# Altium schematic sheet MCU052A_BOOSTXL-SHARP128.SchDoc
size 431 x 279 mm; Date: Not shown in title block; ApprovedBy: Not shown in title block; CheckedBy: Not shown in title block; Author: Not shown in title block; CompanyName: Not shown in title block; Engineer: Not shown in title block; Organization: Not shown in title block; Address1: Not shown in title block; Address2: Not shown in title block; Address3: Not shown in title block; Address4: Not shown in title block; DocumentNumber: 1; Revision: Use project parameter SCH_Rev; SheetNumber: 1; SheetTotal: 2; PageSetup: Record=PageOptions¦CenterHorizontal=True¦CenterVertical=True¦PrintScale=1.00¦XCorrection=1.00¦YCorrection=1.00¦PrintKind=0¦BorderSize=5000000¦LeftOffset=0¦BottomOffset=0¦Orientation=2¦PaperLength=1000¦PaperWidth=1000¦Scale=100¦PaperSource=15¦PrintQuality=600¦MediaType=1¦DitherType=10¦PaperKind=Letter¦PrintScaleMode=1
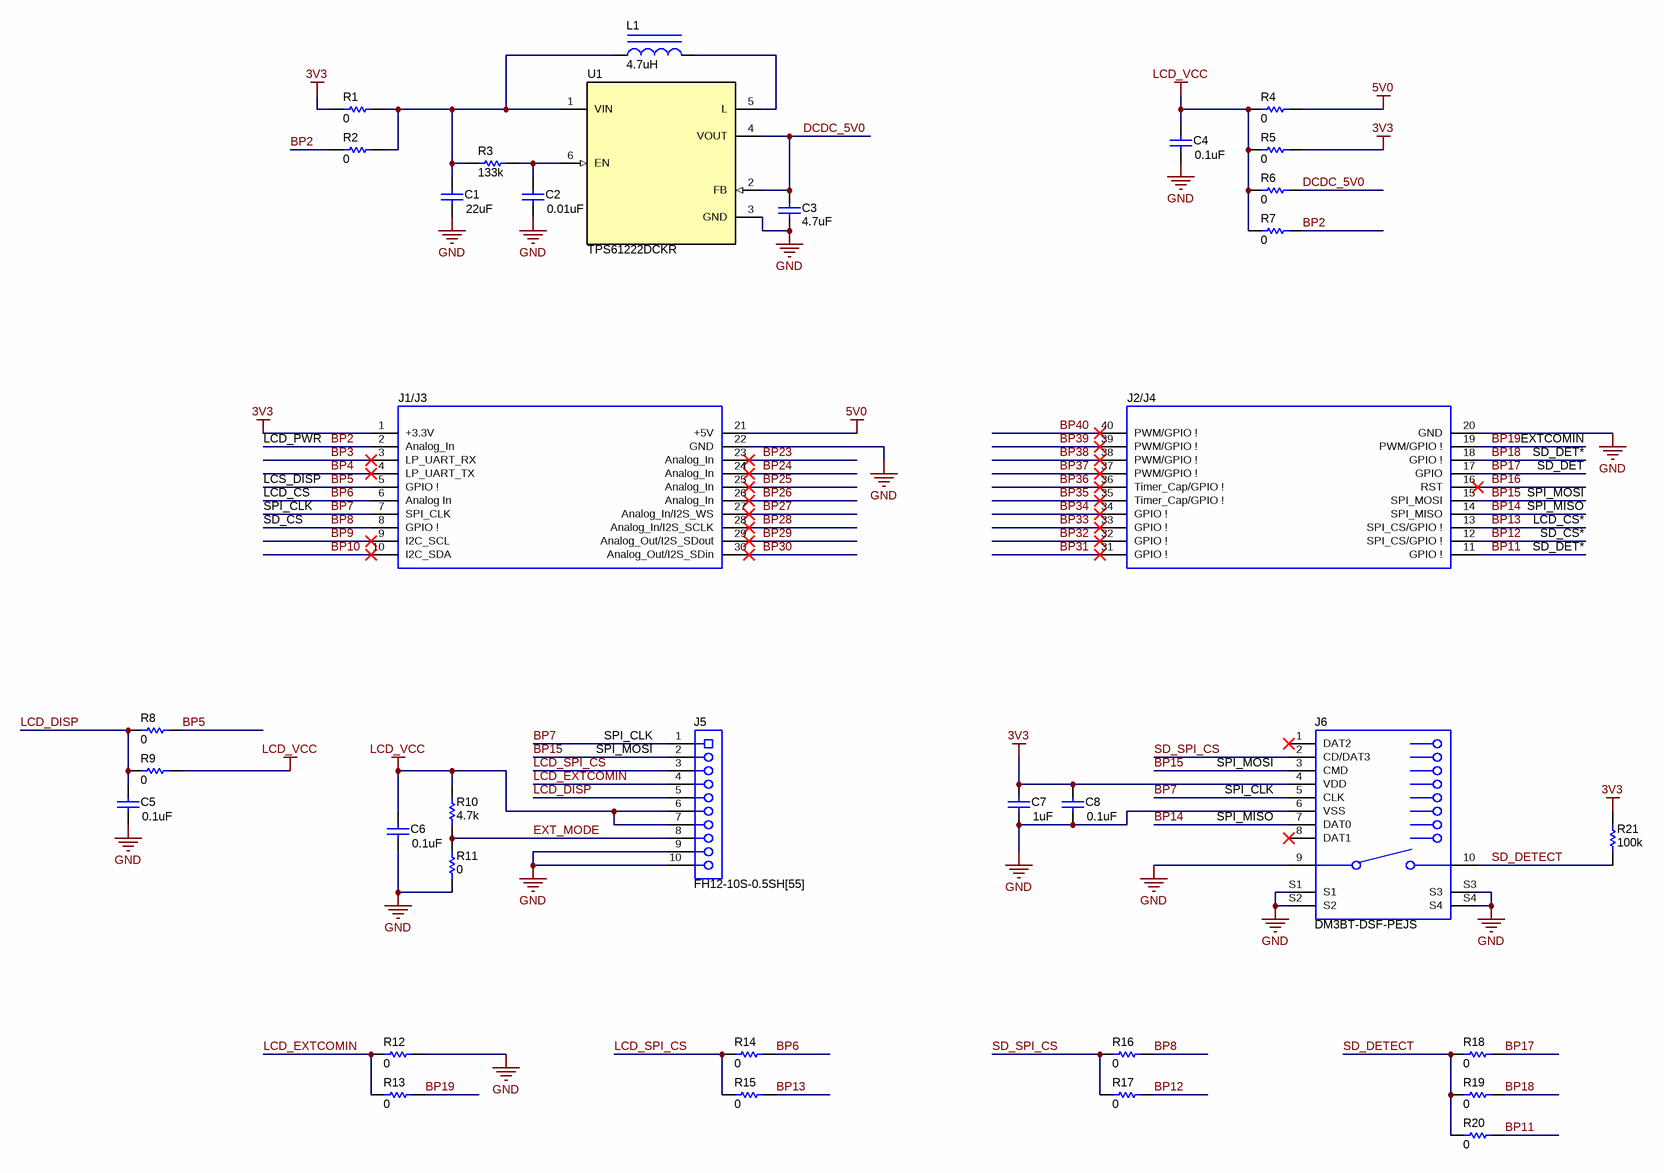
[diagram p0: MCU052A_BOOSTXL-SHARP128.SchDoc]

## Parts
C1  ValueDisplayed: 22uF  [0603]  (hidden comment: GRM188R61A226ME15D)
C2  ValueDisplayed: 0.01uF  [0603]  (hidden comment: GRM188R71E103KA01D)
C3  ValueDisplayed: 4.7uF  [0603]  (hidden comment: GRM188C71A475KE11D)
C4  ValueDisplayed: 0.1uF  [0402]  (hidden comment: GRM155R71A104KA01D)
C5  ValueDisplayed: 0.1uF  [0402]  (hidden comment: GRM155R71A104KA01D)
C6  ValueDisplayed: 0.1uF  [0402]  (hidden comment: GRM155R71A104KA01D)
C7  ValueDisplayed: 1uF  [0603]  (hidden comment: GRM188R71C105KA12D)
C8  ValueDisplayed: 0.1uF  [0402]  (hidden comment: GRM155R71A104KA01D)
J1/J3  SSQ-110-03-T-D  [BoosterPack_40pin_J1J3]  (value not drawn)
J2/J4  SSQ-110-03-T-D  [BoosterPack_40pin_J2J4]  (value not drawn)
J5  FH12-10S-0.5SH[55]  [Hirose_FH12-10S-0_5SH[55]]
J6  DM3BT-DSF-PEJS  [Hirose_DM3BT-DSF-PEJS]
L1  ValueDisplayed: 4.7uH  [EPL3015]  (hidden comment: EPL3015-472MLB)
R1  ValueDisplayed: 0  [0603]  (hidden comment: CRCW06030000Z0EA)
R2  ValueDisplayed: 0  [0603]  (hidden comment: CRCW06030000Z0EA)
R3  ValueDisplayed: 133k  [0603]  (hidden comment: CRCW0603133KFKEA)
R4  ValueDisplayed: 0  [0603]  (hidden comment: CRCW06030000Z0EA)
R5  ValueDisplayed: 0  [0603]  (hidden comment: CRCW06030000Z0EA)
R6  ValueDisplayed: 0  [0603]  (hidden comment: CRCW06030000Z0EA)
R7  ValueDisplayed: 0  [0603]  (hidden comment: CRCW06030000Z0EA)
R8  ValueDisplayed: 0  [0603]  (hidden comment: CRCW06030000Z0EA)
R9  ValueDisplayed: 0  [0603]  (hidden comment: CRCW06030000Z0EA)
R10  ValueDisplayed: 4.7k  [0603]  (hidden comment: CRCW06034K70JNEA)
R11  ValueDisplayed: 0  [0603]  (hidden comment: CRCW06030000Z0EA)
R12  ValueDisplayed: 0  [0603]  (hidden comment: CRCW06030000Z0EA)
R13  ValueDisplayed: 0  [0603]  (hidden comment: CRCW06030000Z0EA)
R14  ValueDisplayed: 0  [0603]  (hidden comment: CRCW06030000Z0EA)
R15  ValueDisplayed: 0  [0603]  (hidden comment: CRCW06030000Z0EA)
R16  ValueDisplayed: 0  [0603]  (hidden comment: CRCW06030000Z0EA)
R17  ValueDisplayed: 0  [0603]  (hidden comment: CRCW06030000Z0EA)
R18  ValueDisplayed: 0  [0603]  (hidden comment: CRCW06030000Z0EA)
R19  ValueDisplayed: 0  [0603]  (hidden comment: CRCW06030000Z0EA)
R20  ValueDisplayed: 0  [0603]  (hidden comment: CRCW06030000Z0EA)
R21  ValueDisplayed: 100k  [0603]  (hidden comment: CRCW0603100KFKEA)
U1  TPS61222DCKR  [DCK0006A_N]

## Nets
3V3: C7.1 C8.1 J1/J3.1(+3.3V) J6.4(VDD) R1.1 R5.2 R21.2
5V0: J1/J3.21(+5V) R4.2
GND: C1.2 C2.2 C3.2 C4.2 C5.2 C6.2 C7.2 C8.2 J1/J3.22(GND) J2/J4.20(GND) J5.9 J5.10 J6.6(VSS) J6.9(A) J6.S1 J6.S2 J6.S3 J6.S4 R11.1 R12.2 U1.3(GND)
LCD_VCC: C4.1 C6.1 J5.6 J5.7 R4.1 R5.1 R6.1 R7.1 R9.2 R10.2
BP2: J1/J3.2(Analog_In) R2.1 R7.2
BP3: J1/J3.3(LP_UART_RX)
BP4: J1/J3.4(LP_UART_TX)
BP5: J1/J3.5(GPIO_!) R8.2
BP6: J1/J3.6(Analog_In) R14.2
BP7: J1/J3.7(SPI_CLK) J5.1 J6.5(CLK)
BP8: J1/J3.8(GPIO_!) R16.2
BP9: J1/J3.9(I2C_SCL)
BP10: J1/J3.10(I2C_SDA)
BP11: J2/J4.11(GPIO_!) R20.2
BP12: J2/J4.12(SPI_CS/GPIO_!) R17.2
BP13: J2/J4.13(SPI_CS/GPIO_!) R15.2
BP14: J2/J4.14(SPI_MISO) J6.7(DAT0)
BP15: J2/J4.15(SPI_MOSI) J5.2 J6.3(CMD)
BP16: J2/J4.16(RST)
BP17: J2/J4.17(GPIO) R18.2
BP18: J2/J4.18(GPIO_!) R19.2
BP19: J2/J4.19(PWM/GPIO_!) R13.2
BP23: J1/J3.23(Analog_In)
BP24: J1/J3.24(Analog_In)
BP25: J1/J3.25(Analog_In)
BP26: J1/J3.26(Analog_In)
BP27: J1/J3.27(Analog_In/I2S_WS)
BP28: J1/J3.28(Analog_In/I2S_SCLK)
BP29: J1/J3.29(Analog_Out/I2S_SDout)
BP30: J1/J3.30(Analog_Out/I2S_SDin)
BP31: J2/J4.31(GPIO_!)
BP32: J2/J4.32(GPIO_!)
BP33: J2/J4.33(GPIO_!)
BP34: J2/J4.34(GPIO_!)
BP35: J2/J4.35(Timer_Cap/GPIO_!)
BP36: J2/J4.36(Timer_Cap/GPIO_!)
BP37: J2/J4.37(PWM/GPIO_!)
BP38: J2/J4.38(PWM/GPIO_!)
BP39: J2/J4.39(PWM/GPIO_!)
BP40: J2/J4.40(PWM/GPIO_!)
DCDC_5V0: C3.1 R6.2 U1.2(FB) U1.4(VOUT)
EXT_MODE: J5.8 R10.1 R11.2
LCD_DISP: C5.1 J5.5 R8.1 R9.1
LCD_EXTCOMIN: J5.4 R12.1 R13.1
LCD_SPI_CS: J5.3 R14.1 R15.1
SD_DETECT: J6.10(B) R18.1 R19.1 R20.1 R21.1
SD_SPI_CS: J6.2(CD/DAT3) R16.1 R17.1
NetC1_1: C1.1 L1.1 R1.2 R2.2 R3.1 U1.1(VIN)
NetC2_1: C2.1 R3.2 U1.6(EN)
NetL1_2: L1.2 U1.5(L)

Not connected (* = marked no-connect by the designer): J6 1(DAT2)* 8(DAT1)*

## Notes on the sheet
- LCD_PWR
- SD_DET*
- EXTCOMIN
- SPI_CLK
- LCD_CS
- SD_CS
- LCS_DISP
- SPI_MISO
- SPI_MOSI
- LCD_CS*
- SD_DET
- SD_CS*
- (near J5) SPI_CLK
- (near J5) SPI_MOSI
- (near J6) SPI_MOSI
- (near J6) SPI_CLK
- (near J6) SPI_MISO

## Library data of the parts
C1 = CMP-0007324-5: CAP, CERM, 22 uF, 10 V, +/- 20%, X5R, 0603; Manufacturer: MuRata; TaMin_C: -55°C; Polarized: N; SizeAreaWB_mm2: 4.68; Value1: Unknown; U/M: EA; Value: 22uF; TaMax_C: 85°C; SizeZ_mm: 1; SizeX_mm: 1.6; SizeY_mm: 0.8; Value2: 10V; SizeArea_mm2: 1.28; Cap_F: 22µF; AEC Category: Q200
C2 = CMP-0007403-4: CAP, CERM, 0.01 uF, 25 V, +/- 10%, X7R, 0603; Manufacturer: MuRata; TaMin_C: -55°C; Polarized: N; SizeAreaWB_mm2: 4.68; Value1: Unknown; U/M: EA; Value: 0.01uF; TaMax_C: 125°C; SizeZ_mm: 1; SizeX_mm: 1.6; SizeY_mm: 0.8; Value2: 25V; SizeArea_mm2: 1.28; Cap_F: 10nF; AEC Category: Q200
C3 = CMP-0007291-4: CAP, CERM, 4.7 uF, 10 V, +/- 10%, X7S, 0603; Manufacturer: MuRata; TaMin_C: -55°C; Polarized: N; SizeAreaWB_mm2: 4.68; Value1: Unknown; U/M: EA; Value: 4.7uF; TaMax_C: 125°C; SizeZ_mm: 1; SizeX_mm: 1.6; SizeY_mm: 0.8; Value2: 10V; SizeArea_mm2: 1.28; Cap_F: 4.7µF; AEC Category: Q200
C4-C6 C8 = CMP-0006629-2: CAP, CERM, 0.1 uF, 10 V, +/- 10%, X7R, 0402; Manufacturer: MuRata; TaMin_C: -55°C; Polarized: N; SizeAreaWB_mm2: 3; Value1: Unknown; U/M: EA; Value: 0.1uF; TaMax_C: 125°C; SizeZ_mm: 0.6; SizeX_mm: 1; SizeY_mm: 0.5; Value2: 10V; Cap_F: 100nF; AEC Category: Q200
C7 = CMP-0007379-4: CAP, CERM, 1 uF, 16 V, +/- 10%, X7R, 0603; Manufacturer: MuRata; TaMin_C: -55°C; ESR_ohm: 0.011; Polarized: N; SizeAreaWB_mm2: 4.68; Value1: 0.011 ohm; U/M: EA; Value: 1uF; TaMax_C: 125°C; SizeZ_mm: 1; SizeX_mm: 1.6; SizeY_mm: 0.8; Value2: 16V; SizeArea_mm2: 1.28; Cap_F: 1µF; AEC Category: Q200
J1/J3 = CMP-0003837-2: Receptacle, 2.54mm, 10x2, Tin, TH; Alternate PartNumber: CRD-081413-A-G; Manufacturer: Samtec; Alternate Manufacturer: Major League Electronics; Note: Booster Pack 40 pin J1 and J3; Green_Lifecycle: Active; Green_REACh: Incomplete
J2/J4 = CMP-0078266-2: Receptacle, 2.54mm, 10x2, Tin, TH; Alternate PartNumber: CRD-081413-A-G; Manufacturer: Samtec; Alternate Manufacturer: Major League Electronics; Note: Booster Pack 40 pin J2 and J4; Green_REACh: Incomplete; Green_Lifecycle: Active
J5 = CMP-0075009-2: Connector, FPC 10 Pos. 9.1x2.0x5.6 mm; PartNumber: FH12-10S-0.5SH(55); Manufacturer: Hirose Electric Co. Ltd.; CompType: FFC or FPC; CNHeader: False; CT: True
J6 = CMP-0080007-1: Conncetor, micro SD, 8+2 Pos, R/A, SMT; Manufacturer: Hirose Electric Co. Ltd.; Pitch_mm: 1.1; Gender: Female; ContactFinish: Gold; Row_Count: 1; CompType: Connector
L1 = CMP-0060351-1: Inductor, Shielded, Ferrite, 4.7 uH, 1.2 A, 0.14 ohm, SMD; Manufacturer: Coilcraft; Isat: 1.2A @ 30% inductance drop; Irms: 1.4A @ 40C rise; Green_Lifecycle: Not Set; SizeAreaWB_mm2: 16; DCR_ohm: 1.4d; Green_REACh: Incomplete; Value: 4.7uH; Imax_A: 1.2A; SizeZ_mm: 1.55; SizeX_mm: 3; SizeArea_mm2: 9; Ind_H: 4.7µH; AEC Category: Q200
R1 R2 R4-R9 R11-R20 = CMP-0025697-4: RES, 0, 5%, 0.1 W, AEC-Q200 Grade 0, 0603; Manufacturer: Vishay-Dale; Power_W: 100mW; TempCo: 200 ppm/C; Value_Code: 0000; Value: 0; EIA_Code: E24; SizeX_mm: 1.6; SizeY_mm: 0.8; SizeZ_mm: 1; Value2: 0.1W; SizeArea_mm2: 1.28; AEC Qualified: Y; VDC_V: 75V; AEC Category: Q200
R3 = CMP-0022038-4: RES, 133 k, 1%, 0.1 W, AEC-Q200 Grade 0, 0603; Manufacturer: Vishay-Dale; Power_W: 100mW; TempCo: 100 ppm/C; Value: 133k; EIA_Code: E96; SizeX_mm: 1.6; SizeY_mm: 0.8; SizeZ_mm: 1; Value2: 0.1W; SizeArea_mm2: 1.28; AEC Qualified: Y; VDC_V: 75V; AEC Category: Q200; AEC Grade: 0
R10 = CMP-0025817-4: RES, 4.7 k, 5%, 0.1 W, AEC-Q200 Grade 0, 0603; Manufacturer: Vishay-Dale; Power_W: 100mW; TempCo: 200 ppm/C; Value_Code: 4k70; Value: 4.7k; EIA_Code: E24; SizeX_mm: 1.6; SizeY_mm: 0.8; SizeZ_mm: 1; Value2: 0.1W; SizeArea_mm2: 1.28; AEC Qualified: Y; VDC_V: 75V; AEC Category: Q200; AEC Grade: 0
R21 = CMP-0021990-4: RES, 100 k, 1%, 0.1 W, AEC-Q200 Grade 0, 0603; Manufacturer: Vishay-Dale; Power_W: 100mW; TempCo: 100 ppm/C; Value: 100k; EIA_Code: E96; SizeX_mm: 1.6; SizeY_mm: 0.8; SizeZ_mm: 1; Value2: 0.1W; SizeArea_mm2: 1.28; CompType: Resistor; AEC Qualified: Y; VDC_V: 75V; AEC Category: Q200; AEC Grade: 0
U1 = CMP-0067206-3: Tiny Low Input Voltage Boost Converter, DCK0006A (SOT-SC70-6); Alternate PartNumber: TPS61222DCKT; Manufacturer: Texas Instruments; SizeZ_mm: 1.1; SizeX_mm: 2.1; SizeY_mm: 2.0; SizeArea_mm2: 4.2; CompType: IC; SizeAreaWB_mm2: 9.3; AEC Category: Q200; AEC Qualified: N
